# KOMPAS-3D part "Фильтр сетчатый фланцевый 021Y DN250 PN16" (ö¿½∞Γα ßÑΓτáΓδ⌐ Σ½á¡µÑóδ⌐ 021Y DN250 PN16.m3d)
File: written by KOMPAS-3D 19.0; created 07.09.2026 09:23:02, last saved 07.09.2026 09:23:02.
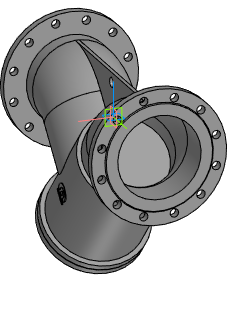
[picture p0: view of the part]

Document properties: Автор: Энергия; Полное имя файла: Z:\3.Личные\sachek\Dendor\_3D для проектировщиков\8.3 Фильтр сетчатый 021Y\021Y_STP\Фильтр сетчатый фланцевый 021Y DN250 PN16.m3d

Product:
- Part/product: Фильтр сетчатый фланцевый 021Y DN250 PN16

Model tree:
1. Операция без истории:1  (labels: Фильтр сетчатый фланцевый 021Y DN250 PN16)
